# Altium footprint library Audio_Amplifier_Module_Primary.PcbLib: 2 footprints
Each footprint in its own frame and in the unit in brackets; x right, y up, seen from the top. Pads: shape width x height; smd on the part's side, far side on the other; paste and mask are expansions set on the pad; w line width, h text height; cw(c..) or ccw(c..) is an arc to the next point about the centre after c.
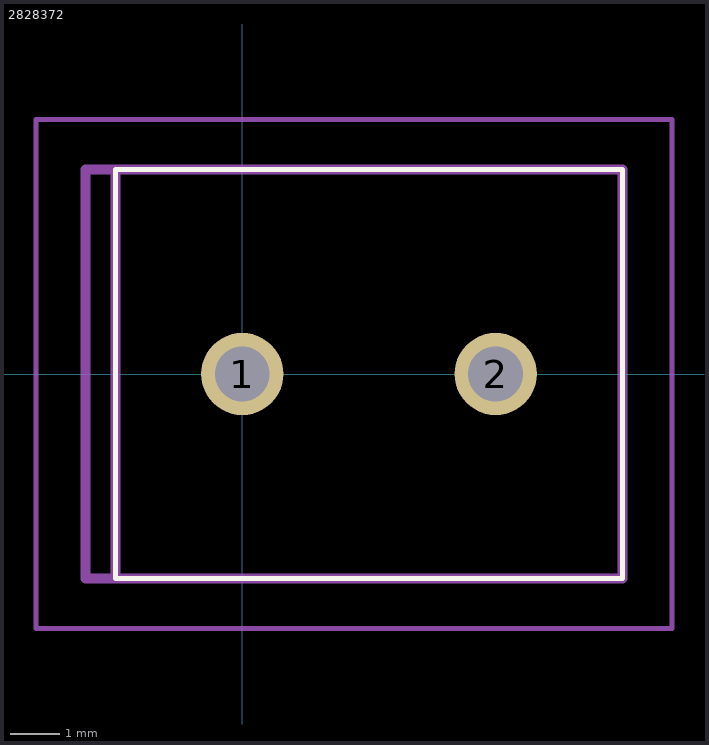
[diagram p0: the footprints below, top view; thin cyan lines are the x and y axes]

## 2828372 [mm]
pads (2):
  round 1.65 hole 1.1: 1(0,0) 2(5.08,0)
Top Overlay:
  lines w0.1: -2.54,-4.1 -2.54,4.1 7.62,4.1 7.62,-4.1 -2.54,-4.1
Mechanical 13:
  lines w0.2: -2.54,-4.1 -3.14,-4.1 -3.14,4.1 -2.54,4.1 ; -2.54,-4.1 -2.54,4.1 ; -2.54,-4.1 -2.54,4.1 ; -2.54,-4.1 7.62,-4.1 7.62,4.1 -2.54,4.1
Mechanical 15:
  lines w0.1: -4.14,-5.1 -4.14,5.1 8.62,5.1 8.62,-5.1 -4.14,-5.1
3D body "282837-2.stp": height 9.84, standoff -3.66, extent -2.51,-4.11 8.25,4.09

## PCBComponent_1 [mm]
